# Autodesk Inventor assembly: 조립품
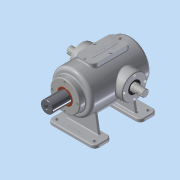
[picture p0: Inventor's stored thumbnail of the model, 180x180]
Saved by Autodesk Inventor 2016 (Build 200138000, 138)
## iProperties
Created: 2018-11
Part Number: 조립품
Material: 일반
Document SubType Name: Assembly
Designer: user
Mass: 8191.27 g
Surface Area: 4241.84 cm^2
Volume: 1855.49 cm^3
Density: 4.41462 g/cm^3
Author: user
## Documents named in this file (15)
- C:\Users\user\Desktop\381121V1013\조립품.iam
- C:\Users\user\Desktop\381121V1013\가변스프링12.ipt
- C:\Users\user\Desktop\381121V1013\베어링 6205.ipt
- 베어링 6205.ipt
- C:\Users\user\Desktop\381121V1013\본체.ipt
- C:\Users\user\Desktop\381121V1013\볼트 M4x0.7.ipt
- C:\Users\user\Desktop\381121V1013\부시.ipt
- C:\Users\user\Desktop\381121V1013\상부커버.ipt
- C:\Users\user\Desktop\381121V1013\슬라이드 커버.ipt
- C:\Users\user\Desktop\381121V1013\슬라이드.ipt
- C:\Users\user\Desktop\381121V1013\오일실.ipt
- 오일실.ipt
- C:\Users\user\Desktop\381121V1013\육각머리볼트 M4.ipt
- C:\Users\user\Desktop\381121V1013\축 커버.ipt
- C:\Users\user\Desktop\381121V1013\편심축.ipt
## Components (13 placed, 2 different names)
1. 가변스프링12:1
2. M4x0.7:1
3. M4x0.7:3
4. M4x0.7:4
5. M4x0.7:5
6. M4x0.7:2
7. M4x0.7:6
8. M4x0.7:7
9. M4x0.7:8
10. M4x0.7:9
11. M4x0.7:10
12. M4x0.7:11
13. M4x0.7:12
